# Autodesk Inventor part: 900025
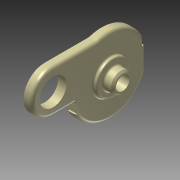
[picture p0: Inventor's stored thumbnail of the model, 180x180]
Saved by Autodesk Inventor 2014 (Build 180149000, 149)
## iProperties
Created: 2007-10
Part Number: 900025
Document SubType Name: Modeling
Designer: TH
Density: 1.13 g/cm^3
Mass: 11.233 g
Surface Area: 57.438 cm^2
Volume: 9.94074 cm^3
Material: Nylon Composite (Nylon, molybdenum disulphide)
Description: MOTOR SIDE COVER
Appearance: Nylon 6
Component Category: Electrical
Author: TH
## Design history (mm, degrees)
node "900684"
  sketch "Sketch1"
    geometry: L1 (0, 0)-(0, -22.5) reference; L2 (0, -22.5)-(-3, -22.5) reference; L3 (-5, -20.5)-(-5, -11) reference; L4 (-6, -10)-(-6, -10) reference; L5 (-7, -9)-(-7, -7) reference; L6 (-8, -6)-(-11.5, -6) reference; L7 (-12.5, -5)-(-12.5, 0) reference; L8 (-12.5, 0)-(0, 0) reference; L9 (-11.5, -6)-(-12.5, -5) reference; A1 r 2 centre (-3, -20.5) between (-5, -20.5) and (-3, -22.5) reference; A2 r 1 centre (-6, -11) between (-5, -11) and (-6, -10) reference; A3 r 1 centre (-6, -9) between (-7, -9) and (-6, -10) reference; A4 r 1 centre (-8, -7) between (-7, -7) and (-8, -6) reference; 4 further points
  sketch "Sketch2"
    geometry: L1 (20, -10.308)-(20, 10.308) reference; L2 (-20, 10.308)-(-20, -10.308) reference; L3 (0, 31.5)-(0, -31.5) reference; A1 r 22.5 centre (0, 0) between (-20, -10.308) and (20, 10.308) reference
  sketch "Sketch3"
    geometry: C1 r 5 at (0, 0) reference; C2 r 4 at (0, 0) reference
  sketch "Sketch4"
    geometry: L1 (-20, 10.308)-(-20, 5.938) reference; L2 (20, -5.938)-(20, -10.308) reference; L3 (20, -10.308)-(18.995, -10.308) reference; L4 (18.995, -10.308)-(18.995, -5.938) reference; L5 (18.995, -5.938)-(20, -5.938) reference; L6 (-18.995, 10.308)-(-20, 10.308) reference; L7 (-20, 5.938)-(-18.995, 5.938) reference; L8 (-18.995, 5.938)-(-18.995, 10.308) reference; L9 (20, 10.308)-(20, -10.308) reference; L10 (-20, -10.308)-(-20, 10.308) reference
body "Solid1"
tag "TaggingFeature2"
feature "DerivedBody::D-900684"
